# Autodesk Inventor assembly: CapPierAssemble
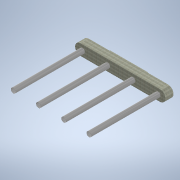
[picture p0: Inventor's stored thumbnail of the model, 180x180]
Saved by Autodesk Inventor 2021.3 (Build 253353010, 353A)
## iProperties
Created: 2021-11
Part Number: CapPierAssemble
Document SubType Name: Assembly
Designer: u1426
Author: u1426
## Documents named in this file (3)
- S:\Bridge_CADD\Other\SampleBridgeInventor\CapPierAssemble.iam
- S:\Bridge_CADD\Other\SampleBridgeInventor\CapPier.ipt
- S:\Bridge_CADD\Other\SampleBridgeInventor\Pile24.ipt
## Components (5 placed, 2 different names)
1. CapPier:1 — Mate:1, Mate:2, Flush:1, Mate:3
2. Pile24:1 — Mate:2, Flush:1, Mate:3
3. Pile24:2
4. Pile24:3
5. Pile24:4
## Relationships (4: Mate 3, Flush 1)
- Mate:1: CapPier:1
- Mate:2: CapPier:1 ↔ Pile24:1
- Flush:1: CapPier:1 ↔ Pile24:1
- Mate:3: CapPier:1 ↔ Pile24:1
